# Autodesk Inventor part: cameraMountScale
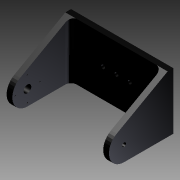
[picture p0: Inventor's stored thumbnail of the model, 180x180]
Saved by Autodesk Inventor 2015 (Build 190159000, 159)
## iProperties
Created: 2015-02
Part Number: cameraMountScale
Material: Generic
Document SubType Name: Modeling
Designer: sungeun
Density: 1 g/cm^3
Appearance: Default
Author: sungeun
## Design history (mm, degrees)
feature "cameraMount"
feature "MeshFeature1"
body "Solid1"
